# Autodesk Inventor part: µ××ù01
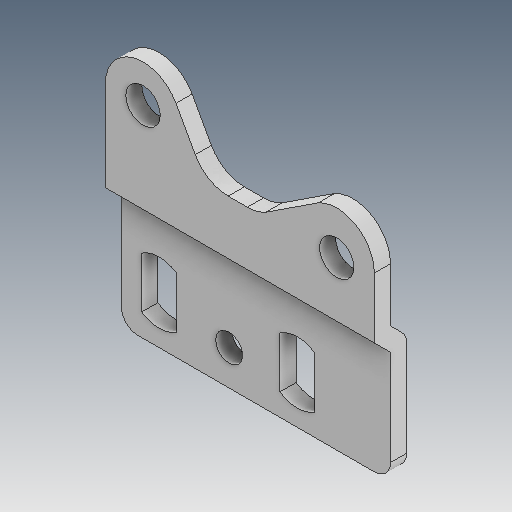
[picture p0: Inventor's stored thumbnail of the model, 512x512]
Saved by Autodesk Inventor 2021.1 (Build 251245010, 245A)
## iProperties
Created: 2020-03
Part Number: µ××ù01
Material: Ogólny
Document SubType Name: Modeling
Designer: user
Density: 1 g/cm^3
Appearance: Domyślna
Author: user
Revision Number: ÈÎºÎ
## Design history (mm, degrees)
feature "ÇÐ³ý-À­Éì2"
node "Bryła1"
